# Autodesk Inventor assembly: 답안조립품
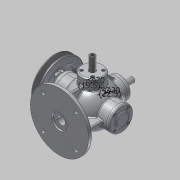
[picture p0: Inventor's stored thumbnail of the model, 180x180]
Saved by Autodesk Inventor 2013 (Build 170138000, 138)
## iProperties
Created: 2016-07
Part Number: 답안조립품
Document SubType Name: Assembly
Designer: dgall
Author: dgall
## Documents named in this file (17)
- C:\Users\dgall\Desktop\360707V1025\답안조립품.iam
- C:\Users\dgall\Desktop\360707V1025\본체.ipt
- C:\Users\dgall\Desktop\360707V1025\본체커버.ipt
- C:\Users\dgall\Desktop\360707V1025\베어링- 6202.ipt
- C:\Users\dgall\Desktop\360707V1025\앞커버.ipt
- C:\Users\dgall\Desktop\360707V1025\뒤커버.ipt
- C:\Users\dgall\Desktop\360707V1025\슬라이드 커버.ipt
- C:\Users\dgall\Desktop\360707V1025\축.ipt
- C:\Users\dgall\Desktop\360707V1025\오일실.ipt
- C:\Users\dgall\Desktop\360707V1025\키-4x4.ipt
- C:\Users\dgall\Desktop\360707V1025\V-벨트풀리.ipt
- C:\Users\dgall\Desktop\360707V1025\와셔 8x17.ipt
- C:\Users\dgall\Desktop\360707V1025\너트-M8x1.ipt
- C:\Users\dgall\Desktop\360707V1025\볼트 M4x0.7.ipt
- C:\Users\dgall\Desktop\360707V1025\스프링1.ipt
- C:\Users\dgall\Desktop\360707V1025\스프링2.ipt
- C:\Users\dgall\Desktop\360707V1025\슬라이드.ipt
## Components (18 placed, 2 different names)
1. V-벨트풀리:1
2. M4x0.7x12:3
3. M4x0.7x12:1
4. M4x0.7x12:6
5. M4x0.7x12:7
6. M4x0.7x12:8
7. M4x0.7x12:4
8. M4x0.7x12:9
9. M4x0.7x12:10
10. M4x0.7x12:11
11. M4x0.7x12:5
12. M4x0.7x12:12
13. M4x0.7x12:13
14. M4x0.7x12:14
15. M4x0.7x12:2
16. M4x0.7x12:15
17. M4x0.7x12:16
18. M4x0.7x12:17
